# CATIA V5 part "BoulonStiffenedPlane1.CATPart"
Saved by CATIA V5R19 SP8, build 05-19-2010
Part number: BoulonStiffenedPlane1
Bounding box of the stored display mesh (mm): x -28 to 24, y 1092 to 1108, z 442 to 458
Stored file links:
  G:\EU_thinkMotion\CFAO_2010\MMS_groupe3\MMS_groupe3\A reprendre\fovide\fovide\BoulonStiffenedPlane1.CATPart
  C:\Users\Rodger\Desktop\Part11.CATPart
  G:\EU_thinkMotion\CFAO_2010\MMS_groupe3\MMS_groupe3\A reprendre\fovide\fovide\fovide.CATProduct
  G:\EU_thinkMotion\CFAO_2010\MMS_groupe3\MMS_groupe3\A reprendre\fovide\fovide\Stiffened Plane 28.CATPart
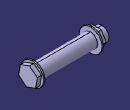
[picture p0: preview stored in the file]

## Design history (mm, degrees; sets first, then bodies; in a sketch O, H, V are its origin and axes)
Parameters
  Diametre = 10 mm
  Longueur = 40 mm
Set1
  DatumSurface1: linked copy from another document
  Point1: linked copy from another document
Body1 (main body)
Body2
  Sketch1 on DatumSurface1, origin (20, 0, 20), H (0, 0, -1), V (0, 1, 0)
    circle A1 centre (-430, 1100) radius 8
    point P1 (-430, 1100)
    reference projected point E1 (-430, 1100) from Point1
    radius A1 = 8 {= Diametre *8/10}
    coincidence: P1 E1
  Pad1: profile Sketch1, direction (1, 0, 0), length 1
  Sketch2 on end face of Pad1, origin (21, 0, 22), H (0, 0, -1), V (0, 1, 0)
    point P1 (-428, 1100)
    point P2 (-425.5061, 1093.4593)
    point P3 (-421.0887, 1098.8894)
    point P4 (-423.5825, 1105.4301)
    point P5 (-430.4939, 1106.5407)
    point P6 (-434.9113, 1101.1106)
    point P7 (-432.4175, 1094.5699)
    point P8 (-423.2974, 1096.1744)
    line L1 (-425.5061, 1093.4593) -> (-421.0887, 1098.8894)
    line L2 (-421.0887, 1098.8894) -> (-423.5825, 1105.4301)
    line L3 (-423.5825, 1105.4301) -> (-430.4939, 1106.5407)
    line L4 (-430.4939, 1106.5407) -> (-434.9113, 1101.1106)
    line L5 (-434.9113, 1101.1106) -> (-432.4175, 1094.5699)
    line L6 (-432.4175, 1094.5699) -> (-425.5061, 1093.4593)
    construction line L7 (-428, 1100) -> (-423.2974, 1096.1744)
    construction circle A1 centre (-428, 1100) radius 7
    construction arc A2 centre (-434.9113, 1101.1106) radius 7 from (-430.4939, 1106.5407) to (-432.4175, 1094.5699) cw
    construction arc A3 centre (-421.0887, 1098.8894) radius 7 from (-423.5825, 1105.4301) to (-425.5061, 1093.4593) ccw
    reference projected point E1 (-428, 1100) from Point1
    radius A1 = 7 {= Diametre *7/10}
    coincidence: A1 P2, A1 P3, A1 P4, A1 P5, A1 P6, A1 P7, A2 P1, A3 P1, P1 E1
    midpoint: P8 L1
    parallelism: L1 L4
  Pad2: profile Sketch2, direction (1, 0, 0), length 3
  Sketch3 on start face of Pad1, origin (20, 0, 20), H (0, 0, -1), V (0, -1, 0)
    circle A1 centre (-430, -1100) radius 5
    point P1 (-430, -1100)
    reference projected point E1 (-430, -1100) from Point1
    radius A1 = 5 {= Diametre /2}
    coincidence: P1 E1
  Pad3: profile Sketch3, direction (-1, 0, 0), length 40 {= Longueur}
  Sketch4 on end face of Pad3, origin (-20, 0, -60), H (0, 0, -1), V (0, -1, 0)
    circle A1 centre (-510, -1100) radius 8
    point P1 (-510, -1100)
    reference projected point E1 (-510, -1100) from Point1
    radius A1 = 8 {= Diametre *8/10}
    coincidence: P1 E1
  Pad4: profile Sketch4, direction (-1, 0, 0), length 1
  Sketch5 on end face of Pad4, origin (-21, 0, -62), H (0, 0, -1), V (0, -1, 0)
    point P1 (-512, -1100)
    point P2 (-512.0478, -1106.9998)
    point P3 (-505.9619, -1103.5413)
    point P4 (-505.9141, -1096.5415)
    point P5 (-511.9522, -1093.0002)
    point P6 (-518.0381, -1096.4587)
    point P7 (-518.0859, -1103.4585)
    point P8 (-509.0048, -1105.2706)
    line L1 (-512.0478, -1106.9998) -> (-505.9619, -1103.5413)
    line L2 (-505.9619, -1103.5413) -> (-505.9141, -1096.5415)
    line L3 (-505.9141, -1096.5415) -> (-511.9522, -1093.0002)
    line L4 (-511.9522, -1093.0002) -> (-518.0381, -1096.4587)
    line L5 (-518.0381, -1096.4587) -> (-518.0859, -1103.4585)
    line L6 (-518.0859, -1103.4585) -> (-512.0478, -1106.9998)
    construction line L7 (-512, -1100) -> (-509.0048, -1105.2706)
    construction circle A1 centre (-512, -1100) radius 7
    construction arc A2 centre (-518.0381, -1096.4587) radius 7 from (-511.9522, -1093.0002) to (-518.0859, -1103.4585) cw
    construction arc A3 centre (-505.9619, -1103.5413) radius 7 from (-505.9141, -1096.5415) to (-512.0478, -1106.9998) ccw
    reference projected point E1 (-512, -1100) from Point1
    radius A1 = 7 {= Diametre *7/10}
    coincidence: A1 P2, A1 P3, A1 P4, A1 P5, A1 P6, A1 P7, A2 P1, A3 P1, P1 E1
    midpoint: P8 L1
    parallelism: L1 L4
  Pad5: profile Sketch5, direction (-1, 0, 0), length 3
  Sketch6 on end face of Pad5, origin (-24, 0, -68), H (0, 0, -1), V (0, -1, 0)
    circle A1 centre (-518, -1100) radius 5
    point P1 (-518, -1100)
    reference projected point E1 (-518, -1100) from Point1
    radius A1 = 5 {= Diametre /2}
    coincidence: P1 E1
  Pad6: profile Sketch6, direction (-1, 0, 0), length 4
